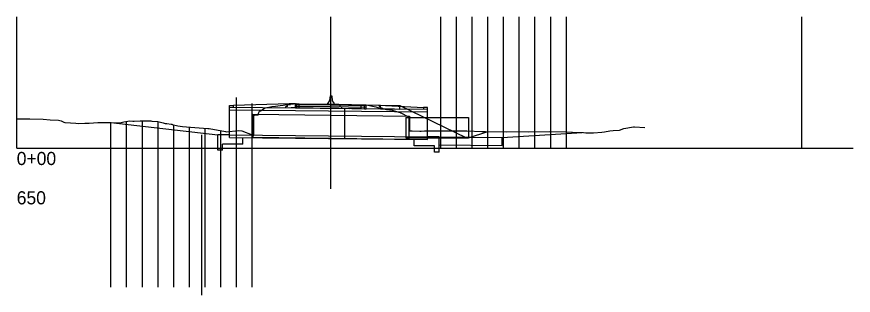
# Model space of a CAD drawing. Extents: x 2283072 to 2287933, y 586198 to 587702.
# Drawn here: x 2285064.9 to 2285331.3, y 586974.4 to 587062.9 of the extents above; entities that cross this region are included whole.
import ezdxf

# ---------------------------------------------------------------- set-up
doc = ezdxf.new("R2010")
doc.units = 0
for name, color, linetype in [('_CIVIL_CONSTRUCTION', 7, 'Continuous'), ('Default', 7, 'Continuous'), ('DT_X_Break_Line', 7, 'Continuous'), ('DT_X_Contour_Major', 7, 'Continuous'), ('DT_X_Contour_Minor', 7, 'Continuous'), ('DT_X_Contour_Text', 7, 'Continuous'), ('DT_X_Terrain_Boundary', 7, 'Continuous'), ('DT_X_Triangles', 7, 'Continuous'), ('HY_X_Water_Edge', 7, 'Continuous'), ('PV_X_Driveway', 7, 'Continuous'), ('RD_X_Fence', 7, 'Continuous'), ('SV_P_Control_Cells_Set', 7, 'Continuous'), ('UT_X_Misc_Cells', 7, 'Continuous')]:
    doc.layers.add(name, color=color, linetype=linetype)

msp = doc.modelspace()

# ---------------------------------------------------------------- linework, layer by layer
at = {"layer": '_CIVIL_CONSTRUCTION'}
for p, q in [((2285164.74, 587037.85), (2285164.55, 587036.27)), ((2285164.74, 587037.85), (2285165.24, 587037.84)), ((2285165.24, 587037.84), (2285165.38, 587036.25)), ((2285163.94, 587035.2), (2285163.95, 587035.45)), ((2285163.94, 587035.2), (2285165.94, 587035.16)), ((2285164.55, 587036.27), (2285163.95, 587035.45)), ((2285165.38, 587036.25), (2285165.95, 587035.41)), ((2285165.94, 587035.16), (2285165.95, 587035.41))]:
    msp.add_line(p, q, dxfattribs=at)
at = {"layer": 'Default'}
for q in [(2285064.94, 587062.95), (2285331.27, 587021.13)]:
    msp.add_line((2285064.94, 587021.13), q, dxfattribs=at)
at = {"layer": 'DT_X_Break_Line'}
for p, q in [((2285151.65, 587034.98), (2285151.15, 587034.96)), ((2285151.15, 587034.46), (2285151.15, 587034.96)), ((2285153.69, 587035.31), (2285151.65, 587035.23)), ((2285151.65, 587034.98), (2285151.65, 587035.23)), ((2285153.69, 587034.06), (2285153.69, 587035.31)), ((2285153.69, 587035.31), (2285164.94, 587035.18)), ((2285153.69, 587035.06), (2285164.94, 587034.93)), ((2285153.69, 587034.56), (2285164.94, 587034.43)), ((2285164.94, 587035.18), (2285176.19, 587034.97)), ((2285164.94, 587034.93), (2285176.19, 587034.72)), ((2285167.4, 587034.88), (2285167.4, 587035.13)), ((2285167.91, 587034.37), (2285167.91, 587034.87)), ((2285176.19, 587033.76), (2285176.19, 587034.97)), ((2285176.19, 587034.97), (2285180.28, 587034.8)), ((2285180.28, 587034.55), (2285180.28, 587034.8)), ((2285180.28, 587034.55), (2285180.78, 587034.53)), ((2285151.15, 587034.46), (2285150.65, 587034.44)), ((2285150.65, 587034.02), (2285150.65, 587034.44)), ((2285153.69, 587034.06), (2285152.27, 587034)), ((2285153.69, 587034.06), (2285164.94, 587033.93)), ((2285164.94, 587034.43), (2285176.19, 587034.22)), ((2285164.94, 587033.93), (2285170.99, 587033.81)), ((2285168.42, 587033.84), (2285168.42, 587034.36)), ((2285180.78, 587034.03), (2285180.78, 587034.53)), ((2285180.78, 587034.03), (2285181.28, 587034)), ((2285181.28, 587033.71), (2285181.28, 587034))]:
    msp.add_line(p, q, dxfattribs=at)
at = {"layer": 'DT_X_Contour_Major'}
for p, q in [((2285132.69, 587034.2), (2285132.69, 587034.7)), ((2285132.69, 587034.7), (2285133.94, 587034.7)), ((2285133.94, 587034.18), (2285133.94, 587034.7)), ((2285132.69, 587034.2), (2285195.69, 587033.57)), ((2285132.69, 587024.53), (2285132.69, 587034.2)), ((2285132.69, 587033.36), (2285195.69, 587032.73)), ((2285169.44, 587024.16), (2285169.44, 587033.83)), ((2285195.69, 587034.07), (2285194.44, 587034.07)), ((2285194.44, 587034.07), (2285194.44, 587033.58)), ((2285195.69, 587033.57), (2285195.69, 587034.07)), ((2285195.69, 587023.9), (2285195.69, 587033.57)), ((2285128.94, 587020.49), (2285128.94, 587025.36)), ((2285132.69, 587025.36), (2285128.94, 587025.36)), ((2285132.69, 587025.36), (2285195.69, 587024.73)), ((2285132.69, 587024.53), (2285195.69, 587023.9)), ((2285136.94, 587022.49), (2285136.94, 587024.49)), ((2285191.44, 587021.94), (2285191.44, 587023.94)), ((2285199.44, 587024.73), (2285195.69, 587024.73)), ((2285199.44, 587019.94), (2285199.44, 587024.73)), ((2285136.94, 587022.49), (2285130.44, 587022.49)), ((2285130.44, 587020.49), (2285130.44, 587022.49)), ((2285197.94, 587021.94), (2285191.44, 587021.94)), ((2285197.94, 587019.94), (2285197.94, 587021.94)), ((2285130.44, 587020.49), (2285128.94, 587020.49)), ((2285199.44, 587019.94), (2285197.94, 587019.94))]:
    msp.add_line(p, q, dxfattribs=at)
at = {"layer": 'DT_X_Contour_Minor'}
msp.add_line((2285164.94, 587008.22), (2285164.94, 587062.95), dxfattribs=at)
at = {"layer": 'DT_X_Contour_Text'}
for p, q in [((2285154.11, 587033.97), (2285154.11, 587035.24)), ((2285154.83, 587033.99), (2285154.83, 587035.26)), ((2285175.61, 587033.7), (2285175.61, 587034.97)), ((2285176.21, 587033.64), (2285176.21, 587034.91))]:
    msp.add_line(p, q, dxfattribs=at)
msp.add_lwpolyline([(2285154.11, 587033.97), (2285154.83, 587033.99), (2285161.56, 587033.91), (2285164.96, 587033.88), (2285167.48, 587033.85), (2285175.61, 587033.7), (2285176.21, 587033.64)], dxfattribs=at)
at = {"layer": 'DT_X_Terrain_Boundary'}
for p, q in [((2285174.65, 587034.99), (2285186.92, 587034.76)), ((2285174.65, 587033.78), (2285174.65, 587034.99)), ((2285186.92, 587033.55), (2285186.92, 587034.76)), ((2285186.92, 587034.76), (2285208.11, 587024.43)), ((2285174.65, 587033.78), (2285186.92, 587033.55)), ((2285208.79, 587024.43), (2285214.9, 587026.46))]:
    msp.add_line(p, q, dxfattribs=at)
at = {"layer": 'DT_X_Triangles'}
for p, q in [((2285154.11, 587035.24), (2285152.11, 587035.04)), ((2285176.21, 587034.91), (2285178.21, 587034.51))]:
    msp.add_line(p, q, dxfattribs=at)
for points in [[(2285064.94, 587030.45), (2285068.84, 587030.45), (2285069.03, 587030.46), (2285069.16, 587030.45), (2285073.33, 587030.4), (2285075.55, 587030.19), (2285078.19, 587030.08), (2285079.1, 587029.87), (2285079.96, 587029.45), (2285080.29, 587029.33), (2285080.33, 587029.32), (2285083.73, 587029.07), (2285084.65, 587029.06), (2285086.61, 587029.08), (2285086.98, 587029.09), (2285087.99, 587029.14), (2285090.73, 587029.32), (2285091.9, 587029.31), (2285095.04, 587029.28), (2285096, 587029.23), (2285096.96, 587029.24), (2285097.82, 587029.24), (2285099.05, 587029.55), (2285100.94, 587029.84), (2285101.92, 587029.8), (2285102.33, 587029.8), (2285104.2, 587029.81), (2285106.66, 587029.84), (2285107.62, 587029.83), (2285107.99, 587029.8), (2285109.87, 587029.65), (2285111.61, 587029.18), (2285112.19, 587029.04), (2285112.75, 587028.98), (2285114.06, 587028.8), (2285114.38, 587028.75), (2285114.45, 587028.73), (2285116.19, 587028.26), (2285117.68, 587028.04), (2285120.26, 587027.88), (2285125.74, 587027.41), (2285126.21, 587027.39), (2285131.42, 587026.45), (2285131.59, 587026.41), (2285131.63, 587026.41), (2285135.54, 587026.75), (2285136.58, 587026.69), (2285139.88, 587025.36), (2285140.43, 587025.29), (2285140.44, 587027.58), (2285140.46, 587030.86), (2285140.46, 587031.67), (2285140.69, 587031.71), (2285141.83, 587031.73), (2285142.06, 587032.54), (2285142.27, 587032.93), (2285142.56, 587033.07), (2285144.04, 587033.94), (2285144.61, 587034.1), (2285145.21, 587034.24), (2285146.11, 587034.44), (2285147.34, 587034.51), (2285148.81, 587034.7), (2285149.75, 587034.87), (2285150.88, 587035.04), (2285151.8, 587035.06), (2285152.11, 587035.04)], [(2285154.11, 587035.24), (2285154.11, 587035.24), (2285154.15, 587035.24), (2285154.83, 587035.26), (2285161.56, 587035.18), (2285164.96, 587035.15), (2285167.48, 587035.12), (2285175.61, 587034.97), (2285176.21, 587034.91), (2285176.21, 587034.91)], [(2285178.21, 587034.51), (2285179.32, 587034.26), (2285179.6, 587034.21), (2285179.86, 587034.15), (2285179.95, 587034.13), (2285181.48, 587033.74), (2285182.71, 587033.5), (2285183.67, 587033.33), (2285184.45, 587033.21), (2285185.07, 587033.09), (2285187.06, 587032.48), (2285187.13, 587032.46), (2285187.14, 587032.45), (2285187.25, 587032.41), (2285187.82, 587032.13), (2285189.02, 587031.48), (2285189.3, 587031.39), (2285189.51, 587031.39), (2285189.99, 587031.34), (2285190.02, 587027.68), (2285190.03, 587026.69), (2285190.14, 587026.66), (2285190.86, 587026.67), (2285193.28, 587026.6), (2285193.66, 587026.59), (2285194.78, 587026.64), (2285198.28, 587026.71), (2285199.1, 587026.7), (2285199.31, 587026.72), (2285199.42, 587026.73), (2285202.54, 587026.66), (2285206.02, 587026.68), (2285208.23, 587026.65), (2285212.99, 587026.51), (2285214.2, 587026.48), (2285220.84, 587026.35), (2285224.73, 587026.44), (2285227.87, 587026.39), (2285234.57, 587026.46), (2285239.91, 587026.35), (2285241.93, 587026.26), (2285245.39, 587026.11), (2285246.08, 587026.09), (2285246.39, 587026.08), (2285248.61, 587026.01), (2285251.2, 587026.24), (2285252.09, 587026.4), (2285253.73, 587026.7), (2285254.85, 587026.82), (2285256.86, 587026.94), (2285258.23, 587027.46), (2285261.25, 587027.97), (2285261.6, 587027.97), (2285261.6, 587027.97), (2285264.94, 587027.7)]]:
    msp.add_lwpolyline(points, dxfattribs=at)
at = {"layer": 'HY_X_Water_Edge'}
for p, q in [((2285199.94, 587021.13), (2285199.94, 587062.95)), ((2285204.94, 587021.13), (2285204.94, 587062.95)), ((2285209.94, 587021.13), (2285209.94, 587062.95)), ((2285214.94, 587021.13), (2285214.94, 587062.95)), ((2285219.94, 587021.13), (2285219.94, 587062.95)), ((2285224.94, 587021.13), (2285224.94, 587062.95)), ((2285229.94, 587021.13), (2285229.94, 587062.95)), ((2285234.94, 587021.13), (2285234.94, 587062.95)), ((2285239.94, 587021.13), (2285239.94, 587062.95)), ((2285314.94, 587021.13), (2285314.94, 587062.95)), ((2285134.94, 586976.92), (2285134.94, 587037.32)), ((2285139.94, 586976.92), (2285139.94, 587035.37)), ((2285151.65, 587034.96), (2285151.65, 587034.96)), ((2285094.94, 586976.92), (2285094.94, 587029.28)), ((2285099.94, 586976.92), (2285099.94, 587029.69)), ((2285104.94, 586976.92), (2285104.94, 587029.82)), ((2285109.94, 586976.92), (2285109.94, 587029.63)), ((2285114.94, 586976.92), (2285114.94, 587028.59)), ((2285119.94, 586976.92), (2285119.94, 587027.9)), ((2285124.94, 586976.92), (2285124.94, 587027.48)), ((2285129.94, 586976.92), (2285129.94, 587026.71)), ((2285123.86, 586974.4), (2285123.86, 587025.38))]:
    msp.add_line(p, q, dxfattribs=at)
at = {"layer": 'PV_X_Driveway'}
for p, q in [((2285188.79, 587030.93), (2285208.79, 587030.93)), ((2285188.79, 587030.93), (2285188.79, 587024.43)), ((2285208.79, 587030.93), (2285208.79, 587024.43)), ((2285188.79, 587024.43), (2285208.79, 587024.43))]:
    msp.add_line(p, q, dxfattribs=at)
at = {"layer": 'RD_X_Fence'}
for p, q in [((2285199.44, 587024.73), (2285219.44, 587024.53)), ((2285219.44, 587022.03), (2285219.44, 587024.53)), ((2285199.44, 587022.23), (2285219.44, 587022.03))]:
    msp.add_line(p, q, dxfattribs=at)
at = {"layer": 'SV_P_Control_Cells_Set'}
for p, q in [((2285140.12, 587031.96), (2285189.79, 587031.35)), ((2285140.12, 587031.96), (2285140.12, 587024.62)), ((2285189.79, 587031.35), (2285189.79, 587024.01)), ((2285140.12, 587024.62), (2285189.79, 587024.01))]:
    msp.add_line(p, q, dxfattribs=at)
at = {"layer": 'UT_X_Misc_Cells'}
for p, q in [((2285151.65, 587035.23), (2285133.94, 587034.7)), ((2285094.94, 587029.28), (2285128.94, 587025.36)), ((2285219.44, 587024.53), (2285244.94, 587026.13))]:
    msp.add_line(p, q, dxfattribs=at)
msp.add_lwpolyline([(2285180.28, 587034.8), (2285180.28, 587034.8), (2285194.44, 587034.07)], dxfattribs=at)

# ---------------------------------------------------------------- texts
at = {"layer": 'Default'}
for s, p in [('0+00', (2285064.94, 587015.8)), ('650', (2285064.94, 587003.3))]:
    msp.add_text(s, height=4.167, dxfattribs=at).set_placement(p)

doc.saveas('drawing.dxf')
